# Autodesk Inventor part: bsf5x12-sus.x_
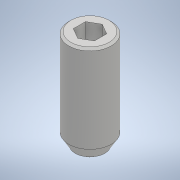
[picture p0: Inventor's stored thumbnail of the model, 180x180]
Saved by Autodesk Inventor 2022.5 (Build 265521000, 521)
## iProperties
Created: 2020-01
Part Number: bsf5x12-sus.x_
Material: 一般
Document SubType Name: Modeling
Designer: ImaoCorp
Density: 1 g/cm^3
Appearance: 既定
Sending System: SOLIDWORKS 2018-2018316
MC: AMD64
MC_MODEL: Intel64 Family 6 Model 60 Stepping 3, GenuineIntel
OS: Windows_NT
FRU: Parasolid Version 30.0, build 310,  6- 8-2018
FORMAT: text
GUISE: transmit
KEY: bsf5x12-sus
FILE: bsf5x12-sus.x_t
DATE: Thu Jan 23 16:48:46 2020
Author: ImaoCorp
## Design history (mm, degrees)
feature "Base1"
node "ソリッド1"
